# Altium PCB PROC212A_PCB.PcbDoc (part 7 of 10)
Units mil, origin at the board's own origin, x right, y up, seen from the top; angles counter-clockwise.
Board outline 3032.48 x 3598.78 mil, 4 copper layers (Top Layer, L2_GND1, L3_PWR1, Bottom Layer), stack 60.58 mil thick; 432 components, 310 nets, 7775 pads, 1236 vias.
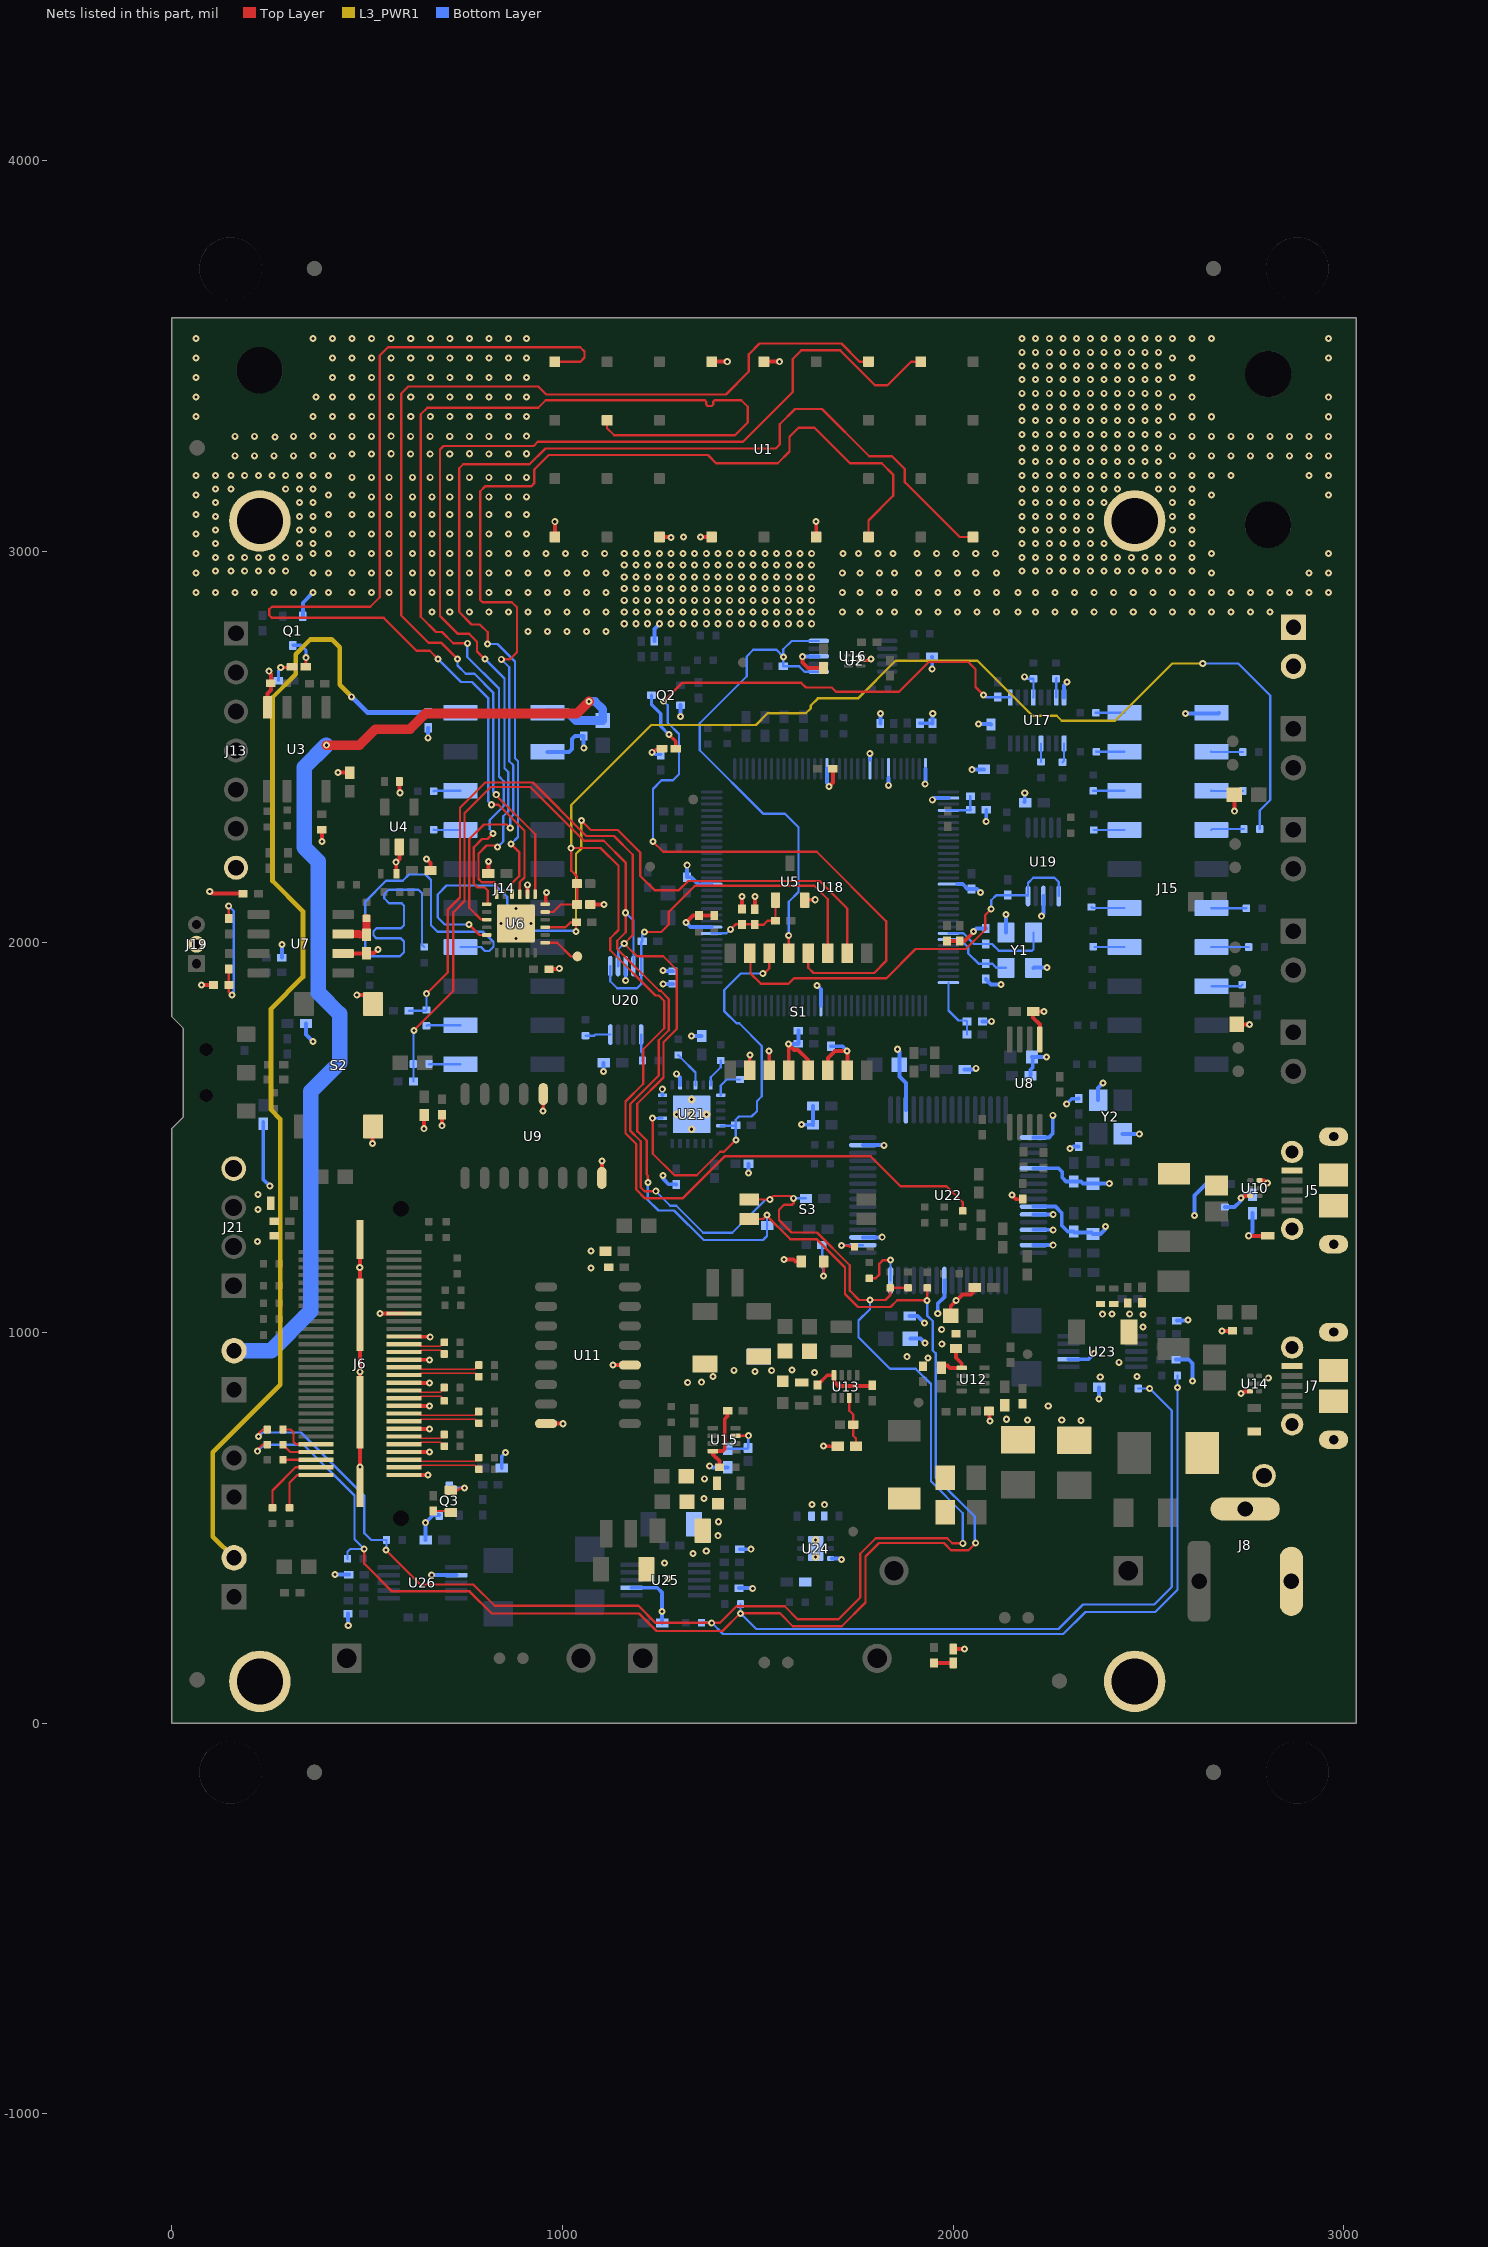
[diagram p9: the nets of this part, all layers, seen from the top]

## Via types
v1: diameter 18, hole 8, Top Layer to Bottom Layer, tented both sides, 1224 vias
v2: diameter 19.68, hole 7.87, Top Layer to Bottom Layer, tented both sides, 10 vias
v3: diameter 19.68, hole 7.87, Top Layer to Bottom Layer, 2 vias

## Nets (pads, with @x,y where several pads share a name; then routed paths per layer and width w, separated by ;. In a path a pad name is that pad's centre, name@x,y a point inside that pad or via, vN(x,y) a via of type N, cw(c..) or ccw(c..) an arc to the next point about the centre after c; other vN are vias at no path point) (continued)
GND: C1.1 C2.2 C3.2 C4.1 C5.2 C6.2 C7.2 C8.1 C9.1 C10.1 C11.2 C12.1 C13.1 C14.1 C15.1 C16.1 C17.2 C18.2 C19.2 C20.2 C21.1 C22.1 C23.2 C24.2 C25.2 C26.2 C27.2 C28.1 C29.2 C30.2 C31.1 C32.1 C33.1 C34.2 C35.2 C36.2 C37.2 C38.2 C39.2 C40.1 C41.2 C42.2 C43.1 C44.2 C45.2 C46.2 C47.1 C48.2 C49.2 C50.2 C51.2 C52.2 C53.2 C54.2 C55.1 C56.1 C57.2 C58.2 C59.2 C60.2 C61.2 C62.1 C63.1 C64.1 C65.1 C66.1 C67.1 C68.2 C69.2 C70.2 C71.1 C72.2 C73.2 C74.2 C75.1 C76.2 C77.2 C78.2 C79.2 C80.2 C81.2 C82.2 C83.1 C84.2 C85.2 C86.1 C87.2 C88.1 C89.2 C90.1 C91.2 C92.2 C93.1 C94.1 C95.2 C96.2 D4.1 D7.2 D9.2 J5.5 J5.6 J5.7 J5.8 J5.9 J5.10 J5.11 J6.18 J6.24 J6.30 J6.36 J6.42 J6.48 J6.54 J6.60 J6.MP1 J6.MP2 J6.MP3 J6.MP4 J7.5 J7.6 J7.7 J7.8 J7.9 J7.10 J7.11 J8.2 J8.3 J12.1 J12.2 J13.7 J14.4 J15.2 J19.2 J21.4 pad.TH2 pad.TH9 Q1.2 Q2.2 Q3.2 R3.1 R10.1 R13.1 R19.1 R25.2 R38.1 R63.1 R70.1 R72.1 R76.1 R84.1 R99.1 R120.2 R121.2 R123.1 R131.1 R152.1 R154.1 R176.1 R179.1 R182.2 R183.1 R193.1 R196.1 R199.1 R201.1 R207.1 R211.1 R213.1 R216.1 R220.1 S1.10 S1.11 S1.12 S1.13 S1.14 S1.15 S2.1 S2.2 TP7.1 U1.5 U1.6 U1.25 U1.27 U1.28 U1.30 U2.2 U3.4 U4.2 U5.2 U6.2 U6.24 U6.25 U7.2 U8.5 U9.8 U9.12 U10.3 U11.8 U11.12 U12.1 U13.8 U14.3 U15.8 U16.3 U17.8 U18.10 U18.17 U18.48 U18.55 U18.58 U18.64 U18.66 U18.80 U18.114 U19.3 U20.3 U21.2 U21.24 U21.25 U22.1 U22.5 U22.10 U22.11 U22.13 U22.15 U22.25 U22.35 U22.47 U22.51 U23.7 U24.3 U24.7 U25.7 U26.7 Y1.2 Y1.4 Y2.2 Y2.4 | length 8755.6
  Top Layer w8: U2.2@1763.78,2720.77 1783.13,2720.77 1787.14,2724.78 v1(1789.84,2724.78)
  Top Layer w10: v1(75.66,1889.9) 75.77,1890.01 C16.1@106.45,1890.01 ; v1(96.82,2129.42) 98.98,2129.42 104.03,2124.37 181.9,2124.37 C8.1@182.24,2124.03 ; U3.4@244.65,2601.15 244.65,2636.96 253.16,2645.47 R3.1@253.16,2662.39 253.16,2687.16 248.41,2691.91 v1(248.41,2693.53) ; R10.1@383.76,2287.35 383.76,2257.74 v1(384.05,2257.44) ; v1(425.53,2434.22) 425.75,2434 454.84,2434 C2.2@455.06,2433.78 ; U7.2@438.19,1970.7 497.48,1970.7 C15.1@498.41,1971.63 517.8,1971.63 v1(527.62,1981.45) ; v1(473.31,1864.09) 493.45,1864.09 515.04,1842.5 S2.1@515.04,1841.16 ; v1(480.87,1166.55) 481.52,1167.2 481.52,1206.04 J6.MP2@481.52,1013.52 ; J6.MP4@481.52,603.48 J6.MP3@481.52,796 J6.MP2@481.52,1046 ; v1(513.82,1484.39) 513.82,1526.94 S2.2@515.04,1528.17 ; v1(532.68,1049.1) 532.76,1049.03 594.23,1049.03 J6.18@594.31,1048.95 ; v1(573.87,2204.56) 582.13,2212.83 U4.2@582.13,2243.72 ; v1@574.3,2203.27 574.3,2175.54 C7.2@574.73,2175.11 ; C4.1@582.13,2411.48 583.04,2410.58 583.04,2383.26 v1(583.95,2382.35) ; J6.30@594.31,930.84 594.59,930.56 659.61,930.56 v1(659.89,930.29) ; J6.24@594.31,989.89 594.61,989.59 661.02,989.59 v1(661.32,989.3) ; J6.54@594.59,694.34 659.61,694.34 v1(659.89,694.07) ; J6.48@594.59,753.4 659.61,753.4 v1(659.89,753.12) ; J6.42@594.59,812.45 659.61,812.45 v1(659.89,812.18) ; J6.36@594.59,871.51 659.61,871.51 v1(659.89,871.23) ; J6.60@594.89,635.57 v1(655.32,635.58) ; v1(645.34,1522.12) 645.75,1522.52 C19.2@645.75,1557.03 ; v1(651.84,2212.32) 662.01,2202.15 R13.1@662.01,2183.31 ; v1(691.36,1529.81) 691.44,1529.88 691.44,1558.05 C20.2@691.51,1558.12 ; C6.2@810.41,2176.63 v1(810.41,2206.7) ; U6.2@910.26,2122.38 v1@910.28,2146.64 ; v1(950.36,1567.11) 950.64,1567.4 U9.12@950.64,1610.78 ; U6.24@955.53,2096.79 956.44,2096.79 957.17,2097.51 957.17,2125.24 v1(958.8,2126.87) ; U11.8@957.91,767.07 1001.29,767.07 v1(1001.58,766.79) ; R25.2@965.16,1930.78 965.87,1931.49 991.09,1931.49 v1(991.81,1932.21) ; U1.30@980.3,3037.2 v1@980.3,3076.35 ; R19.1@1070.97,2096.32 1105.71,2096.32 v1(1106.02,2096) ; U9.8@1100.64,1396.21 1100.64,1439.59 v1(1100.93,1439.88) ; v1(1128.81,917.36) 1129.1,917.07 U11.12@1172.48,917.07 ; U1.28@1248.02,3037.2 1274.99,3037.2 1276.62,3035.56 v1(1277.44,3035.56) ; v1(1316.07,2050.12) 1334.21,2068.25 C12.1@1349.45,2068.25 C11.2@1388.42,2068.25 ; v1(1353.24,3037.2) U1.27@1381.88,3037.2 ; U1.6@1378.64,3486.02 U1.6@1381.88,3486.02 v1(1421.79,3486.02) ; C50.2@1402.25,655.05 1402.25,671.29 1393.81,679.73 1393.01,679.73 1384.83,687.91 U15.8@1384.83,696.48 1409.69,696.48 1415.31,702.09 1415.31,779.14 1422.89,786.72 R76.1@1422.89,799.7 ; C9.1@1459.75,2084.66 1459.75,2116.11 v1(1459.94,2116.3) ; S1.10@1479.28,1671.68 1479.47,1671.87 1479.47,1710.47 v1(1479.66,1710.66) ; C10.1@1493.1,2084.79 1493.1,2116.24 v1(1493.29,2116.43) ; U1.5@1512.5,3486.02 U1.5@1515.73,3486.02 v1(1555.64,3486.02) ; v1(1528.75,1721.29) 1529.28,1720.77 S1.11@1529.28,1671.68 ; v1(1567.22,1187.13) 1592.17,1187.13 1597.06,1182.23 D4.1@1611.54,1182.23 ; v1(1578.3,1738.61) v1@1579.28,1737.63 ; S1.12@1579.28,1671.68 v1@1579.28,1737.63 ; v1(1614.53,2730.62) 1614.53,2715.83 1628.83,2701.53 C1.1@1668.49,2701.53 ; U5.2@1620.02,2107.41 1621.04,2108.43 v1(1646.99,2108.43) ; S1.13@1629.28,1671.68 1629.28,1697.58 1603.02,1723.84 1593.07,1723.84 v1@1579.28,1737.63 ; v1(1649.4,3076.5) 1649.59,3076.31 U1.25@1649.59,3037.2 ; C45.2@1653.1,866.18 1677.87,890.95 U13.8@1695.16,890.95 ; v1(1668.41,709.37) 1668.68,709.1 R84.1@1704.35,709.1 ; S1.14@1679.28,1671.68 1679.28,1702.97 1697.6,1721.29 v1(1728.75,1721.29) 1729.28,1720.77 S1.15@1729.28,1671.68 ; v1(1682.8,2398.85) 1692.1,2408.14 C3.2@1692.1,2443.69 ; U13.8@1694.55,890.35 1695.16,889.74 1695.16,874.8 1706.4,863.56 R70.1@1793.3,863.56 ; C40.1@1962.08,916.02 1985.54,916.02 1991.77,909.79 U12.1@2022.21,909.79 2022.21,920.9 2007.31,935.8 C39.2@2007.31,959.66 ; C13.1@1984.32,2003.06 2016.7,2003.06 C14.1@2017.02,2002.74 2029.36,2002.74 2051.88,2025.26 v1(2051.88,2026.83) ; C34.2@1994.09,1043.01 1994.09,1067.94 2023.69,1097.54 2045.59,1097.54 C27.2@2055.44,1107.39 ; D9.2@2000.53,189.9 2000.9,190.28 v1(2028.93,190.28) ; R72.1@2091.94,799.35 2093.12,798.17 2093.12,775.28 v1(2094.31,774.09) v1@2096.39,774.09 ; v1(2150.85,1352.14) 2161.38,1341.61 2178.03,1341.61 R38.1@2178.64,1342.22 ; U8.5@2222.05,1750.44 2222.05,1789.43 2205.08,1806.39 C18.2@2205.08,1822.34 2232.41,1822.34 v1(2232.71,1822.63) ; v1(2688.12,1004.64) v1(2688.12,1004.64) 2715.7,1004.59 R63.1@2715.76,1004.53 ; C5.2@2719.97,2376.89 2720.31,2376.55 v1(2720.31,2335.09) ; C17.2@2726.37,1789.73 2726.76,1789.34 v1(2758.48,1789.34) ; v1(2737.41,844.69) 2740.69,844.69 2745.8,849.81 U14.3@2760.01,849.81 ; v1@2757.22,1247.89 C22.1@2805.53,1247.89 ; U10.3@2784.61,1389.7 2795.9,1389.7 2802.85,1382.75 v1(2805.22,1382.75)
  Bottom Layer w8: 1347.35,2148.41 U18.17@1381.98,2148.41
  Bottom Layer w10: R176.1@233.75,1538.93 233.75,1391.93 v1(250.57,1375.12) ; R152.1@281.35,1960.2 281.35,1993.77 v1(281.56,1993.98) ; Q1.2@335.12,2834.44 335.13,2868.91 v1(361.31,2895.09) ; C68.2@343.2,1791.49 343.2,1763.83 v1(361.2,1745.83) ; v1(417.93,380.81) 418.43,380.3 R211.1@452.93,380.3 ; R220.1@451.06,280.61 451.06,250.95 v1(451.43,250.59) ; C95.2@649.67,469.17 v1(649.63,513.39) v1(649.63,513.39) 668.95,532.71 Q3.2@684.5,532.71 ; v1(655.31,2523.09) 655.91,2523.7 655.91,2548.05 C58.2@656.51,2548.65 ; v1(665.06,379.04) 665.22,379.2 U26.7@728.08,379.2 ; R201.1@844.37,653.22 844.37,683.48 v1(854.19,693.3) ; J14.4@961.45,2487.22 1016.67,2487.22 1023.95,2494.5 1023.95,2519.75 1032.12,2527.92 C60.2@1054.07,2527.92 1054.07,2497.2 v1(1054.54,2496.73) ; v1(1104.58,1668.43) 1104.58,1690.24 C76.2@1105.48,1691.14 ; v1(1161.87,1901.55) U20.3@1161.85,1938.43 ; U25.7@1176.87,346.87 1242.61,346.87 1254.34,335.13 v1(1254.34,285.8) 1254.81,285.33 1254.81,257.36 C96.2@1255.28,256.9 ; R99.1@1235.04,2770.65 1235.04,2802.06 v1(1248.07,2815.09) ; v1(1255.47,1623.3) 1255.47,1608.45 U21.24@1255.75,1608.17 ; v1(1256.93,1402.16) 1258.46,1400.63 1258.46,1393.08 1271.59,1379.95 1290.59,1379.95 R182.2@1290.96,1379.59 ; v1(1257.56,1927.68) 1258.79,1926.46 1281.47,1926.46 R154.1@1282.7,1925.23 ; v1(1257.8,1893.15) v1(1257.8,1893.15) 1282.8,1893.21 C67.1@1282.86,1893.26 ; v1(1291.68,1662.85) 1301.03,1653.5 U21.2@1301.03,1633.76 ; v1(1302.24,2577.12) 1302.39,2577.27 Q2.2@1302.39,2606.61 ; v1(1316.07,2050.12) 1328.01,2038.18 U18.10@1381.98,2038.18 ; v1(1319.24,2196.86) 1319.24,2166.5 C64.1@1318.67,2165.92 1329.84,2165.92 1347.35,2148.41 ; v1(1330.48,1759.57) C72.2@1356.27,1759.57 ; v1(1376.89,659.05) 1379.6,659.05 1383.6,655.04 R199.1@1423.17,655.04 ; R216.1@1452.02,345.76 1486.52,345.76 v1(1487.02,345.25) ; R207.1@1453.89,445.45 v1(1482.96,445.5) ; R179.1@1476.27,1432.5 1476.27,1408.81 v1(1476.55,1408.54) ; v1(1578.3,1738.61) 1578.84,1739.15 1603.28,1739.15 C73.2@1603.82,1739.69 C71.1@1603.82,1773.19 ; v1(1611.5,1532.71) 1611.78,1532.43 1641,1532.43 C81.2@1641.28,1532.15 1641.28,1580.43 C80.2@1641.12,1580.58 ; v1(1614.53,2730.62) 1615.34,2731.44 1655.57,2731.44 U16.3@1655.91,2731.78 ; v1(1652.07,1888.59) 1661.51,1879.15 U18.114@1661.51,1837.39 ; U18.48@1677.26,2443.69 1677.26,2407.1 1682.8,2401.55 v1(1682.8,2398.85) ; C70.2@1687.52,1733.29 1716.76,1733.29 v1(1728.75,1721.29) ; U24.3@1689.31,421.71 1710.18,421.71 1712.53,419.35 v1@1714.05,419.35 ; U22.35@1769.04,1243.77 1817.86,1243.77 v1(1818.51,1244.42) ; U22.47@1769.04,1480 1822.81,1480 v1(1823.09,1479.72) ; v1(1786.73,2483.2) 1787.43,2482.5 U18.55@1787.43,2467.25 ; R123.1@1813.42,2559.71 1813.68,2559.97 1813.68,2584.76 v1(1813.94,2585.02) ; U18.58@1834.8,2420.13 1834.8,2401.62 v1(1834.93,2401.49) ; v1(1858.09,1725.63) 1858.09,1724.82 1862.74,1720.17 1862.74,1686.03 C75.1@1862.4,1685.69 1862.4,1655.69 1879.27,1638.82 U22.51@1879.27,1570.55 ; C89.2@1888.78,1042.92 1909.16,1042.92 v1(1927.14,1024.94) ; C90.1@1890.74,984.52 1917.09,984.52 v1(1928.5,973.11) ; R120.2@1915.24,2560.24 R121.2@1947.24,2560.24 ; v1(1928.72,2405.11) 1929.16,2405.56 1929.16,2443.62 U18.64@1929.23,2443.69 ; C57.2@1945.98,2729.57 1946.6,2728.95 v1(1946.6,2699.1) ; v1(1946.83,2364.39) 1951.33,2368.88 U18.66@1988.28,2368.88 ; R121.2@1947.45,2560.03 1947.7,2560.29 1947.7,2585.09 v1(1947.96,2585.35) ; v1(1960.74,1048.82) 1960.74,1074.38 1977.7,1091.34 U22.25@1977.7,1133.54 ; U18.80@2011.84,2148.41 2024.84,2148.41 2037.44,2135.82 C63.1@2047.17,2135.82 C63.1@2047.41,2135.82 ; C77.2@2029.7,1673.9 2053.1,1673.9 2056.11,1676.91 v1(2058.27,1676.91) ; C63.1@2047.52,2135.47 2061.69,2135.47 2069.74,2127.42 v1(2069.91,2127.42) ; v1(2048.55,2441.38) 2048.99,2441.82 2078.72,2441.82 R131.1@2079.17,2442.26 ; v1(2051.88,2026.83) 2052.48,2026.83 2060.32,2034.66 C65.1@2084.03,2034.66 ; v1(2065.4,2557.97) 2096.2,2557.97 C59.2@2096.89,2557.27 ; C69.2@2075.24,1796.71 2075.5,1796.97 2098.36,1796.97 v1(2098.58,1797.19) ; C66.1@2084.03,1905.54 2084.03,1903.58 2088.88,1898.73 2089.75,1898.73 2096.77,1891.71 2122.43,1891.71 v1(2122.94,1891.2) ; v1@2084.85,2308.88 C62.1@2084.85,2338.76 ; Y1.4@2135.24,2024.64 v1(2135.24,2070.89) ; C61.2@2183.3,2359.14 2183.48,2359.31 v1(2183.48,2382.19) ; C78.2@2198.09,1657.84 2198.09,1673.11 2203.9,1678.93 2203.9,1703.93 C74.2@2201.84,1705.99 v1(2238.88,1706.01) ; U22.15@2206.05,1224.09 2256.19,1224.09 v1(2256.42,1223.86) ; U22.13@2206.05,1263.46 2256.19,1263.46 v1(2256.42,1263.23) ; U22.11@2206.05,1302.83 2256.19,1302.83 v1(2256.42,1302.6) ; U22.10@2206.05,1322.52 2261.73,1322.52 2278.33,1305.92 2278.33,1274.16 2293.63,1258.85 C86.1@2308.76,1258.85 ; U22.5@2206.05,1420.94 2269.52,1420.94 2279.42,1411.05 2279.42,1396.9 2289.23,1387.08 C83.1@2308.76,1387.08 2327.1,1387.08 2332.6,1381.59 C84.2@2358.23,1381.59 v1@2399.89,1381.59 ; U22.1@2206.05,1499.68 2245.24,1499.68 2255.27,1509.72 v1(2255.27,1556.56) ; Y1.2@2206.11,1934.09 2206.76,1934.73 v1(2240.89,1934.73) ; v1(2226.74,2066.26) 2226.74,2068.42 2231.23,2072.9 U19.3@2231.26,2117.88 ; U17.8@2284.12,2626.66 2284.12,2657.48 2291.94,2665.3 v1(2291.94,2665.92) ; v1(2290.94,1585.83) 2303.94,1598.84 2320.99,1598.84 C79.2@2321.57,1599.41 ; U23.7@2295.6,931.99 2347.2,931.99 v1(2361.31,946.09) ; v1(2299.72,1471.12) 2301.88,1471.12 2307.74,1476.98 C82.2@2321.74,1476.98 ; C86.1@2310.74,1256.87 C87.2@2353.98,1256.87 ; C87.2@2358.23,1252.63 2377.46,1252.63 2388.84,1264.01 2388.84,1269.96 v1(2390.37,1271.49) ; Y2.4@2371.19,1595.56 2371.19,1626.42 v1(2384.07,1639.3) ; v1(2373.83,830.58) 2373.83,860.14 C91.2@2373.9,860.2 ; Y2.2@2434.18,1508.94 2476.75,1508.94 v1(2476.79,1508.98) ; R196.1@2570.75,930.88 2603.52,930.88 2613.36,921.04 v1(2613.36,876.19) ; R193.1@2572.62,1030.57 2573.35,1031.3 2601.2,1031.3 v1(2601.93,1032.03) ; v1(2594.8,2585.05) 2679.11,2585.05 J15.2@2681.27,2587.22 ; v1(2618.26,1300.05) 2618.26,1351.31 2647.55,1380.6 R183.1@2670.87,1380.6 ; v1(2756.96,1248.15) 2766.98,1258.16 C85.2@2766.98,1306.06
  other v1: 1270.09,370.27 1261.48,410.5 1714.1,419.4 1333.64,434.4 1368.05,440.59 1398.31,480.09 1399.66,515.86 1670.92,559.48 1638.64,559.76 1362.13,575.61 1363.58,625.79 481.11,655.97 2327.46,775.49 2278.29,775.93 2190.12,776.82 2136.74,778.31 2243.71,812.17 1320.56,872.61 1355.95,873.16 2807.12,883.5 2376.79,886.2 2470.94,887.29 1385.3,887.99 1645.53,898.39 481.89,899.85 1492.4,900.52 1535.62,902.74 1438.82,903.6 1587.61,904.86 2425.31,924.09 1936.12,935.55 1882.46,938.37 1971.14,971.13 1970.86,1008.13 2486.72,1014.91 2486.76,1046.33 2382.19,1047.21 2452.22,1047.49 2407.38,1047.85 2008.02,1081.86 1072.75,1165.5 1072.54,1209.33 219.39,1233.58 219.9,1315.67 219.9,1354.12 2399.98,1381.49 910.31,2146.66 2084.9,2308.83 911.31,2795.09 961.31,2795.09 1011.31,2795.09 1061.31,2795.09 1111.31,2795.09 1158.07,2815.09 1188.07,2815.09 1218.07,2815.09 1278.07,2815.09 1308.07,2815.09 1338.07,2815.09 1368.07,2815.09 1398.07,2815.09 1428.07,2815.09 1458.07,2815.09 1488.07,2815.09 1518.07,2815.09 1548.07,2815.09 1578.07,2815.09 1608.07,2815.09 1638.07,2815.09 666.31,2845.09 711.31,2845.09 761.31,2845.09 811.31,2845.09 861.31,2845.09 911.31,2845.09 961.31,2845.09 1011.31,2845.09 1061.31,2845.09 1111.31,2845.09 1158.07,2845.09 1188.07,2845.09 1218.07,2845.09 1248.07,2845.09 1278.07,2845.09 1308.07,2845.09 1338.07,2845.09 1368.07,2845.09 1398.07,2845.09 1428.07,2845.09 1458.07,2845.09 1488.07,2845.09 1518.07,2845.09 1548.07,2845.09 1578.07,2845.09 1608.07,2845.09 1638.07,2845.09 1716.31,2845.09 1761.31,2845.09 1811.31,2845.09 1849.77,2845.09 1911.31,2845.09 1961.31,2845.09 2011.31,2845.09 2061.31,2845.09 2111.31,2845.09 2166.31,2845.09 2211.31,2845.09 2261.31,2845.09 2311.31,2845.09 2361.31,2845.09 2411.31,2845.09 2461.31,2845.09 2511.31,2845.09 2561.31,2845.09 2611.31,2845.09 2661.31,2845.09 2711.31,2845.09 2761.31,2845.09 2811.31,2845.09 1158.07,2875.09 1188.07,2875.09 1218.07,2875.09 1248.07,2875.09 1278.07,2875.09 1308.07,2875.09 1338.07,2875.09 1368.07,2875.09 1398.07,2875.09 1428.07,2875.09 1458.07,2875.09 1488.07,2875.09 1518.07,2875.09 1548.07,2875.09 1578.07,2875.09 1608.07,2875.09 1638.07,2875.09 61.31,2895.09 111.31,2895.09 161.31,2895.09 211.31,2895.09 261.31,2895.09 311.31,2895.09 401.31,2895.09 461.31,2895.09 511.31,2895.09 556.31,2895.09 616.31,2895.09 666.31,2895.09 711.31,2895.09 761.31,2895.09 811.31,2895.09 861.31,2895.09 911.31,2895.09 961.31,2895.09 1011.31,2895.09 1061.31,2895.09 1111.31,2895.09 1716.31,2895.09 1761.31,2895.09 1811.31,2895.09 1849.77,2895.09 1911.31,2895.09 1961.31,2895.09 2011.31,2895.09 2061.31,2895.09 2111.31,2895.09 2166.31,2895.09 2211.31,2895.09 2261.31,2895.09 2311.31,2895.09 2361.31,2895.09 2411.31,2895.09 2461.31,2895.09 2511.31,2895.09 2561.31,2895.09 2611.31,2895.09 2661.31,2895.09 2711.31,2895.09 2761.31,2895.09 2811.31,2895.09 2861.31,2895.09 2911.31,2895.09 2961.31,2895.09 1158.07,2905.09 1188.07,2905.09 1218.07,2905.09 1248.07,2905.09 1278.07,2905.09 1308.07,2905.09 1338.07,2905.09 1368.07,2905.09 1398.07,2905.09 1428.07,2905.09 1458.07,2905.09 1488.07,2905.09 1518.07,2905.09 1548.07,2905.09 1578.07,2905.09 1608.07,2905.09 1638.07,2905.09 1158.07,2935.09 1188.07,2935.09 1218.07,2935.09 1248.07,2935.09 1278.07,2935.09 1308.07,2935.09 1338.07,2935.09 1368.07,2935.09 1398.07,2935.09 1428.07,2935.09 1458.07,2935.09 1488.07,2935.09 1518.07,2935.09 1548.07,2935.09 1578.07,2935.09 1608.07,2935.09 1638.07,2935.09 61.31,2945.09 361.31,2945.09 401.31,2945.09 461.31,2945.09 511.31,2945.09 556.31,2945.09 616.31,2945.09 666.31,2945.09 711.31,2945.09 761.31,2945.09 811.31,2945.09 861.31,2945.09 911.31,2945.09 961.31,2945.09 1011.31,2945.09 1061.31,2945.09 1111.31,2945.09 1716.31,2945.09 1761.31,2945.09 1811.31,2945.09 1849.77,2945.09 1911.31,2945.09 1961.31,2945.09 2011.31,2945.09 2058.07,2945.09 2111.31,2945.09 2661.31,2945.09 2911.31,2945.09 2961.31,2945.09 111.31,2950.09 151.31,2950.09 186.31,2950.09 221.31,2950.09 256.31,2950.09 291.31,2950.09 2176.31,2950.09 2211.31,2950.09 2246.31,2950.09 2281.31,2950.09 2316.31,2950.09 2351.31,2950.09 2386.31,2950.09 2421.31,2950.09 2456.31,2950.09 2491.31,2950.09 2526.31,2950.09 2561.31,2950.09 2611.31,2950.09 1158.07,2965.09 1188.07,2965.09 1218.07,2965.09 1248.07,2965.09 1278.07,2965.09 1308.07,2965.09 1338.07,2965.09 1368.07,2965.09 1398.07,2965.09 1428.07,2965.09 1458.07,2965.09 1488.07,2965.09 1518.07,2965.09 1548.07,2965.09 1578.07,2965.09 1608.07,2965.09 1638.07,2965.09 111.31,2985.09 151.31,2985.09 186.31,2985.09 221.31,2985.09 256.31,2985.09 291.31,2985.09 326.31,2985.09 2176.31,2985.09 2211.31,2985.09 2246.31,2985.09 2281.31,2985.09 2316.31,2985.09 2351.31,2985.09 2386.31,2985.09 2421.31,2985.09 2456.31,2985.09 2491.31,2985.09 2526.31,2985.09 2561.31,2985.09 2611.31,2985.09 61.31,2995.09 361.31,2995.09 401.31,2995.09 461.31,2995.09 511.31,2995.09 556.31,2995.09 616.31,2995.09 666.31,2995.09 711.31,2995.09 761.31,2995.09 811.31,2995.09 861.31,2995.09 908.07,2995.09 958.07,2995.09 1008.07,2995.09 1058.07,2995.09 1108.07,2995.09 1158.07,2995.09 1188.07,2995.09 1218.07,2995.09 1248.07,2995.09 1278.07,2995.09 1308.07,2995.09 1338.07,2995.09 1368.07,2995.09 1398.07,2995.09 1428.07,2995.09 1458.07,2995.09 1488.07,2995.09 1518.07,2995.09 1548.07,2995.09 1578.07,2995.09 1608.07,2995.09 1638.07,2995.09 1718.07,2995.09 1758.07,2995.09 1808.07,2995.09 1846.53,2995.09 1908.07,2995.09 1958.07,2995.09 2008.07,2995.09 2058.07,2995.09 2108.07,2995.09 2661.31,2995.09 2961.31,2995.09 111.31,3020.09 326.31,3020.09 361.31,3020.09 2176.31,3020.09 2211.31,3020.09 2246.31,3020.09 2281.31,3020.09 2316.31,3020.09 2351.31,3020.09 2386.31,3020.09 2561.31,3020.09 2611.31,3020.09 1309.69,3037.17 61.31,3045.09 401.31,3045.09 461.31,3045.09 511.31,3045.09 556.31,3045.09 616.31,3045.09 666.31,3045.09 711.31,3045.09 761.31,3045.09 811.31,3045.09 861.31,3045.09 908.07,3045.09 111.31,3055.09 326.31,3055.09 361.31,3055.09 2176.31,3055.09 2211.31,3055.09 2246.31,3055.09 2281.31,3055.09 2316.31,3055.09 2351.31,3055.09 2561.31,3055.09 2611.31,3055.09 980.28,3076.37 111.31,3090.09 326.31,3090.09 361.31,3090.09 2176.31,3090.09 2211.31,3090.09 2246.31,3090.09 2281.31,3090.09 2316.31,3090.09 2351.31,3090.09 2561.31,3090.09 2611.31,3090.09 61.31,3095.09 401.31,3095.09 461.31,3095.09 511.31,3095.09 556.31,3095.09 616.31,3095.09 666.31,3095.09 711.31,3095.09 761.31,3095.09 811.31,3095.09 861.31,3095.09 908.07,3095.09 111.31,3125.09 326.31,3125.09 361.31,3125.09 2176.31,3125.09 2211.31,3125.09 2246.31,3125.09 2281.31,3125.09 2316.31,3125.09 2351.31,3125.09 2386.31,3125.09 2561.31,3125.09 2611.31,3125.09 511.31,3140.09 556.31,3140.09 616.31,3140.09 666.31,3140.09 711.31,3140.09 761.31,3140.09 811.31,3140.09 861.31,3140.09 908.07,3140.09 61.31,3145.09 401.31,3145.09 461.31,3145.09 2661.31,3145.09 2961.31,3145.09 111.31,3160.09 151.31,3160.09 291.31,3160.09 326.31,3160.09 361.31,3160.09 2176.31,3160.09 2211.31,3160.09 2246.31,3160.09 2281.31,3160.09 2316.31,3160.09 2351.31,3160.09 2386.31,3160.09 2421.31,3160.09 2526.31,3160.09 2561.31,3160.09 2611.31,3160.09 461.31,3190.09 511.31,3190.09 556.31,3190.09 616.31,3190.09 661.31,3190.09 711.31,3190.09 761.31,3190.09 811.31,3190.09 861.31,3190.09 908.07,3190.09 61.31,3195.09 111.31,3195.09 151.31,3195.09 186.31,3195.09 221.31,3195.09 256.31,3195.09 291.31,3195.09 326.31,3195.09 361.31,3195.09 401.31,3195.09 2176.31,3195.09 2211.31,3195.09 2246.31,3195.09 2281.31,3195.09 2316.31,3195.09 2351.31,3195.09 2386.31,3195.09 2421.31,3195.09 2456.31,3195.09 2491.31,3195.09 2526.31,3195.09 2561.31,3195.09 2611.31,3195.09 2661.31,3195.09 2711.31,3195.09 2911.31,3195.09 2961.31,3195.09 2176.31,3230.09 2211.31,3230.09 2246.31,3230.09 2281.31,3230.09 2316.31,3230.09 2351.31,3230.09 2386.31,3230.09 2421.31,3230.09 2456.31,3230.09 2491.31,3230.09 2526.31,3230.09 161.31,3245.09 211.31,3245.09 261.31,3245.09 311.31,3245.09 361.43,3245.3 411.31,3245.09 2561.31,3245.09 2611.31,3245.09 2661.31,3245.09 2711.31,3245.09 2761.31,3245.09 2811.31,3245.09 2861.31,3245.09 2911.31,3245.09 2961.31,3245.09 461.31,3250.09 511.31,3250.09 561.43,3250.3 611.31,3250.09 661.31,3250.09 711.31,3250.09 761.43,3250.3 811.31,3250.09 861.31,3250.09 908.19,3250.3 2176.31,3265.09 2211.31,3265.09 2246.31,3265.09 2281.31,3265.09 2316.31,3265.09 2351.31,3265.09 2386.31,3265.09 2421.31,3265.09 2456.31,3265.09 2491.31,3265.09 2526.31,3265.09 263.55,3293.38 161.31,3295.09 211.31,3295.09 311.31,3295.09 361.43,3295.3 411.31,3295.09 461.31,3295.09 511.31,3295.09 561.43,3295.3 611.31,3295.09 661.31,3295.09 711.31,3295.09 761.31,3295.09 811.31,3295.09 861.31,3295.09 908.19,3295.3 2561.31,3295.09 2611.31,3295.09 2661.31,3295.09 2711.31,3295.09 2761.31,3295.09 2811.31,3295.09 2861.31,3295.09 2911.31,3295.09 2961.31,3295.09 2176.31,3300.09 2211.31,3300.09 2246.31,3300.09 2281.31,3300.09 2316.31,3300.09 2351.31,3300.09 2386.31,3300.09 2421.31,3300.09 2456.31,3300.09 2491.31,3300.09 2526.31,3300.09 2176.31,3335.09 2211.31,3335.09 2246.31,3335.09 2281.31,3335.09 2316.31,3335.09 2351.31,3335.09 2386.31,3335.09 2421.31,3335.09 2456.31,3335.09 2491.31,3335.09 2526.31,3335.09 61.43,3345.3 361.43,3345.3 411.43,3345.3 461.43,3345.3 511.43,3345.3 561.43,3345.3 611.43,3345.3 661.43,3345.3 711.43,3345.3 761.43,3345.3 811.43,3345.3 861.43,3345.3 908.19,3345.3 2561.31,3345.09 2611.31,3345.09 2661.31,3345.09 2961.31,3345.09 2176.31,3370.09 2211.31,3370.09 2246.31,3370.09 2281.31,3370.09 2316.31,3370.09 2351.31,3370.09 2386.31,3370.09 2421.31,3370.09 2456.31,3370.09 2491.31,3370.09 2526.31,3370.09 61.43,3395.3 411.43,3395.3 461.43,3395.3 511.43,3395.3 561.43,3395.3 611.43,3395.3 661.43,3395.3 711.43,3395.3 761.43,3395.3 811.43,3395.3 861.43,3395.3 908.19,3395.3 2561.31,3395.09 2611.31,3395.09 2961.31,3395.09 368.41,3396 2176.31,3405.09 2211.31,3405.09 2246.31,3405.09 2281.31,3405.09 2316.31,3405.09 2351.31,3405.09 2386.31,3405.09 2421.31,3405.09 2456.31,3405.09 2491.31,3405.09 2526.31,3405.09 2176.31,3440.09 2211.31,3440.09 2246.31,3440.09 2281.31,3440.09 2316.31,3440.09 2351.31,3440.09 2386.31,3440.09 2421.31,3440.09 2456.31,3440.09 2491.31,3440.09 2526.31,3440.09 61.43,3445.3 411.43,3445.3 461.43,3445.3 511.43,3445.3 561.43,3445.3 611.43,3445.3 661.43,3445.3 711.43,3445.3 761.43,3445.3 811.43,3445.3 861.43,3445.3 908.19,3445.3 2561.31,3445.09 2611.31,3445.09 2176.31,3475.09 2211.31,3475.09 2246.31,3475.09 2281.31,3475.09 2316.31,3475.09 2351.31,3475.09 2386.31,3475.09 2421.31,3475.09 2456.31,3475.09 2491.31,3475.09 2526.31,3475.09 61.43,3495.3 411.43,3495.3 461.43,3495.3 511.43,3495.3 561.43,3495.3 611.43,3495.3 661.43,3495.3 711.43,3495.3 761.43,3495.3 811.43,3495.3 861.43,3495.3 908.19,3495.3 2561.31,3495.09 2611.31,3495.09 2961.31,3495.09 2176.31,3510.09 2211.31,3510.09 2246.31,3510.09 2281.31,3510.09 2316.31,3510.09 2351.31,3510.09 2386.31,3510.09 2421.31,3510.09 2456.31,3510.09 2491.31,3510.09 2526.31,3510.09 61.43,3545.3 361.43,3545.3 411.43,3545.3 461.43,3545.3 511.43,3545.3 561.43,3545.3 611.43,3545.3 661.43,3545.3 711.43,3545.3 761.43,3545.3 811.43,3545.3 861.43,3545.3 908.19,3545.3 2176.31,3545.09 2211.31,3545.09 2246.31,3545.09 2281.31,3545.09 2316.31,3545.09 2351.31,3545.09 2386.31,3545.09 2421.31,3545.09 2456.31,3545.09 2491.31,3545.09 2526.31,3545.09 2561.31,3545.09 2611.31,3545.09 2661.31,3545.09 2961.31,3545.09
  other v2: 1330.55,1520.77 1292.36,1558.96 1330.55,1558.96 1368.74,1558.96 1330.55,1597.15 880.73,2009.38 842.54,2047.57 880.73,2047.57 918.92,2047.57 880.73,2085.76
  other v3: 1648.06,425.69 1648.06,469
HOST_CLK_REQ: TP4.1 U6.19 | length 97.1
  Top Layer w5.9: U6.19@955.53,1998.36 986.8,1998.36 1021.84,1963.33 TP4.1@1038.08,1963.33
HOSTIRQ_FTDI_IN: R51.1 U22.32 | length 142.3
  Top Layer w5.9: R51.1@1785.48,1139.1 1801.71,1139.1 1811.31,1148.69 1811.31,1176.49 1820.55,1185.73 v1(1839.95,1185.73)
  Bottom Layer w5.9: U22.32@1839.93,1133.56 v1(1839.95,1185.73)
HOSTIRQ_FTDI_OUT: R47.1 U22.34 | length 90.6
  Top Layer w5.9: v1(1714.05,1222.79) 1732.71,1222.79 1735.83,1219.68 R47.1@1747.84,1219.68
  Bottom Layer w5.9: v1(1714.05,1222.79) 1715.35,1224.09 U22.34@1769.04,1224.09
I2C_SCL: R55.2 R82.1 R161.1 R162.1 R186.1 R198.2 R209.2 R218.2 S3.2 U20.2 | length 8147.8
  Top Layer w5.9: v1(218.77,696.44) 221.09,698.76 221.09,702.52 231.79,713.22 R82.1@244.09,713.22 ; v1(492.31,446.09) 492.31,408.62 563.38,337.55 762.12,337.55 818.96,280.7 1195.68,280.7 1240.34,236.04 1409.87,236.04 1455.21,281.38 v1(1455.83,281.38) 1556.83,281.38 1589.67,248.53 1715.07,248.53 1775.73,309.19 1775.73,426.98 1810.05,461.31 1976.42,461.31 1994.93,442.8 2039.17,442.8 v1(2057.92,461.55) ; v1(651.65,1867.77) 706.48,1922.6 706.48,2083.27 737.4,2114.18 737.4,2344.18 801.96,2408.74 924.13,2408.74 1061.05,2271.83 1131.57,2271.83 1179.97,2223.43 1179.97,2017.84 v1(1158.1,1995.97) 1190.58,1963.49 1258.06,1963.49 1292.31,1929.24 1292.31,1777.28 1258.39,1743.36 1258.39,1653.28 1191.29,1586.18 1191.29,1516.01 1215.54,1491.76 1215.54,1405.05 1218.53,1402.06 v1(1218.53,1384.25) ; S3.2@1478.09,1290.87 1513.42,1290.87 v1(1523.43,1300.89) ; v1@1523.43,1298.88 1582.86,1239.45 1650.22,1239.45 1723.14,1166.52 1723.14,1099.17 1756.73,1065.58 1840.03,1065.58 1857.15,1082.7 v1(1933.52,1082.7) 1933.91,1083.1 R55.2@1933.91,1114.63
  Bottom Layer w5.9: v1(218.77,696.44) 235.55,713.22 337.18,713.22 467.31,583.09 467.31,471.09 v1@489.31,449.09 ; R209.2@449.3,420.9 449.3,439.09 456.31,446.09 486.72,446.09 486.72,446.5 v1@489.31,449.09 ; v1(492.31,446.09) v1@489.31,449.09 ; R161.1@606.8,1824.45 650.06,1824.45 R162.1@651.56,1825.95 651.56,1867.68 v1(651.65,1867.77) ; U20.2@1142.17,1938.43 1142.74,1939.01 1142.74,1981.91 1156.8,1995.97 v1(1158.1,1995.97) ; v1(1218.53,1384.25) 1218.53,1339.84 1245.42,1312.95 1285.63,1312.95 1361.35,1237.22 1513.02,1237.22 1523.49,1247.69 1523.49,1273.3 R186.1@1524.49,1274.3 1523.43,1275.36 v1(1523.43,1300.89) ; R218.2@1455.65,305.16 1455.65,281.55 v1(1455.83,281.38) ; v1@1456.03,281.38 1496.14,241.27 2270.03,241.27 2332.78,304.01 2515.06,304.01 2559.97,348.92 2559.97,800.82 v1(2503.48,857.31) 2503.19,857.02 R198.2@2474.39,857.02 ; v1(1933.52,1082.7) 1933.52,1043.95 1947.87,1029.6 1947.87,954.56 1955.31,947.12 1955.31,628.87 2055.79,528.39 2055.79,463.68 v1(2057.92,461.55)
I2C_SDA: R53.2 R54.2 R80.1 R172.1 R175.1 R184.1 R197.2 R204.2 R222.2 S3.1 U20.4 | length 8398.9
  Top Layer w5.9: v1(221.52,734.1) 223.84,736.41 223.84,743.65 232.24,752.06 R80.1@244.59,752.06 ; v1(547.65,443.41) 635.96,355.09 771.75,355.09 826.29,300.55 1194.76,300.55 1238.43,256.88 v1@1381.41,256.88 ; v1(619.51,1773.16) 619.51,1774.12 720.58,1875.2 720.58,2076.37 749.3,2105.08 749.3,2330.08 816.06,2396.84 917.52,2396.84 1054.79,2259.58 1105.82,2259.58 1161.59,2203.81 v1(1161.59,2075.1) 1162.03,2074.66 1162.03,2025.28 1140.15,2003.4 1140.15,1982.6 1247.55,1875.2 1251.29,1875.2 1272.2,1854.29 1272.2,1774.36 1246.49,1748.65 1246.49,1658.21 1173.13,1584.85 1173.13,1517.34 1200.58,1489.9 1200.58,1371.46 1209.94,1362.09 v1(1238.89,1362.09) ; v1(1381.98,257.04) 1403.11,257.04 1445.4,299.33 1569.03,299.33 1601.96,266.39 1706.59,266.39 1762.14,321.94 1762.14,434.11 1801.87,473.84 1984.8,473.84 1997.89,460.75 v1(2024.86,460.75) ; S3.1@1478.09,1340.87 v1(1530.66,1340.87) 1539.62,1349.83 1582.64,1349.83 1588.43,1344.05 v1(1591.7,1344.05) 1591.7,1331.29 1587.9,1327.49 1567.38,1327.49 1554.43,1314.53 1554.43,1288.52 1586.4,1256.55 1651.64,1256.55 1735.34,1172.85 1735.34,1107.61 1759.42,1083.53 v1(1787.08,1083.53) 1827.09,1083.53 1838.78,1095.22 R54.2@1838.78,1114.72 1839.21,1115.15 R53.2@1884.81,1115.15
  Bottom Layer w5.9: v1(221.52,734.1) 231.83,744.41 330.21,744.41 492.73,581.89 492.73,486.67 510.23,469.17 R204.2@549.29,469.17 549.29,445.04 v1(547.65,443.41) ; R175.1@618.35,1642.87 618.35,1687.33 R172.1@617.81,1687.88 618.66,1688.73 618.66,1772.3 v1(619.51,1773.16) ; v1(1161.59,2075.1) 1181.54,2055.16 U20.4@1181.54,1938.43 ; v1(1238.89,1362.09) 1276.13,1324.85 1291.35,1324.85 1360.61,1255.59 1434.89,1255.59 1519.16,1339.87 1529.65,1339.87 v1(1530.66,1340.87) ; R222.2@1355.66,256.9 1381.84,256.9 v1(1381.98,257.04) 1410.72,228.29 2282.08,228.29 2338.79,285 2517.89,285 2574.38,341.5 v1(2574.38,859.83) R197.2@2574.38,890.28 ; v1(1591.7,1344.05) 1591.92,1343.83 R184.1@1623.26,1343.83 ; v1(1787.08,1083.53) 1787.08,1060.14 1757.75,1030.8 1757.75,988.5 1838.98,907.26 1904.51,907.26 1943.38,868.39 1943.38,619.28 2024.86,537.8 v1(2024.86,460.75)
LP_SPI_CLK: J14.13 R151.2 | length 1408.5
  Bottom Layer w5.9: R151.2@645.75,1987.25 640.31,1992.69 640.31,2125.09 631.31,2134.09 554.31,2134.09 543.31,2123.09 543.31,2112.09 556.31,2099.09 588.31,2099.09 594.31,2093.09 594.31,2072 594.31,2043.15 586.54,2035.38 523.94,2035.38 516.17,2027.61 516.17,2017.25 523.94,2009.48 586.54,2009.48 594.31,2001.71 594.31,1997.14 594.31,1974.09 583.71,1963.5 510.9,1963.5 495.31,1979.09 495.31,2104.09 548.31,2157.09 590.75,2157.09 606.75,2173.09 649.31,2173.09 663.31,2159.09 663.31,2043.09 680.31,2026.09 797.31,2026.09 823.31,2000.09 823.31,1988.09 812.31,1977.09 801.31,1977.09 791.18,1987.22 J14.13@739.01,1987.22
LP_SPI_CS: J15.16 R158.1 | length 80.4
  Bottom Layer w5.9: J15.16@2661.45,1887.22 2736.33,1887.22 R158.1@2740.23,1891.11
LP_SPI_MISO: J15.14 R150.1 | length 95.6
  Bottom Layer w5.9: J15.14@2661.28,1987.21 R150.1@2756.84,1987.21
LP_SPI_MOSI: J15.12 R147.1 | length 90
  Bottom Layer w5.9: J15.12@2661.27,2087.22 2662.03,2086.46 R147.1@2750.94,2086.46
LVDS_CLK_DC_PWM_AUTO_CTRL_GPIO: U1.14 U6.7 | length 2769.5
  Top Layer w5.9: v1(756.31,2765.09) 720.31,2765.09 691.31,2794.09 676.31,2794.09 637.23,2833.17 637.23,3351.46 654.05,3368.27 658.94,3368.27 659.05,3368.17 937.99,3368.17 957.16,3387.33 1343.5,3387.33 1364.35,3387.33 1367.93,3383.75 1367.93,3376.34 1371.51,3372.76 1382.25,3372.76 1385.83,3376.34 1385.83,3383.75 1389.41,3387.33 1412.6,3387.33 1457.93,3387.33 1474.31,3370.96 1474.31,3330.36 1441.39,3297.44 1132.27,3297.44 1114.16,3315.55 U1.14@1114.16,3336.41 ; U6.7@805.93,2096.79 807.1,2096.79 808.87,2098.56 808.87,2132.05 800.96,2139.96 782.29,2139.96 773.1,2149.16 773.1,2243.09 794.02,2264.01 808.26,2264.01 v1(822.2,2277.95)
  Bottom Layer w5.9: v1(756.31,2765.09) 756.31,2730.09 837.41,2648.99 837.41,2423.89 849.38,2411.92 849.38,2348.55 813.56,2312.73 813.56,2288.87 822.2,2280.23 v1(822.2,2277.95)
LVDS_D0_MODULE_WAKEUP_GPIO_2: U1.3 U6.1 | length 2768.1
  Top Layer w5.9: v1(731.31,2725.09) 690.31,2766.09 657.31,2766.09 586.98,2836.42 586.98,3404.77 604.8,3422.59 937.81,3422.59 958.31,3402.09 1418.31,3402.09 1476.95,3460.74 1476.95,3504.74 1504.6,3532.39 1714.07,3532.39 1760.44,3486.02 U1.3@1783.45,3486.02 ; v1(830.36,2377.32) 830.36,2375.67 929.94,2276.08 U6.1@929.94,2122.38
  Bottom Layer w5.9: v1(731.31,2725.09) 731.31,2707.87 752.21,2686.96 774.44,2686.96 822.31,2639.09 822.31,2385.54 830.36,2377.49 v1(830.36,2377.32)
LVDS_D1_CAN_FD_RX_SPI_RS232_CTRL_GPIO_3: U1.9 U6.3 | length 2767.3
  Top Layer w5.9: v1(681.31,2725.09) 660.31,2746.09 626.14,2746.09 542.14,2830.09 256.31,2830.09 249.31,2837.09 249.31,2852.09 256.03,2858.82 508.03,2858.82 532.16,2882.94 532.16,3501.94 553.26,3523.04 1045.36,3523.04 1056.24,3512.16 1056.24,3496.47 1045.79,3486.02 U1.9@980.3,3486.02 ; v1(818.41,2351.68) 836.13,2351.68 902.52,2285.29 902.52,2165.51 890.7,2153.7 890.7,2144.08 890.67,2144.04 U6.3@890.67,2122.47
  Bottom Layer w5.9: v1(681.31,2725.09) 740.31,2666.09 768.31,2666.09 809.58,2624.82 809.58,2360.51 v1(818.41,2351.68)
LVDS_D2_CAN_FD_TX: U1.22 U6.4 | length 2767.5
  Top Layer w5.9: v1(808.31,2763.09) 808.31,2793.09 788.31,2813.09 767.31,2813.09 735.43,2844.97 735.43,3213.22 745.63,3223.42 915.7,3223.42 956.15,3263.86 1546.08,3263.86 1556.31,3274.09 1556.31,3326.08 1595.32,3365.09 1664.31,3365.09 1785.31,3244.09 1843.31,3244.09 1876.31,3211.09 1876.31,3177.74 2016.85,3037.2 U1.22@2051.17,3037.2 ; v1(868.45,2251.35) 888.93,2230.87 888.93,2168.76 870.89,2150.71 U6.4@870.89,2122.38
  Bottom Layer w5.9: v1(808.31,2763.09) 833.31,2763.09 878.31,2718.09 878.31,2470.58 885.85,2463.03 885.85,2268.75 868.91,2251.81 v1@868.45,2251.81
LVDS_D3_PRESENCE_INDICATION_GPIO: U1.2 U6.6 | length 2767.7
  Top Layer w5.9: v1(801.31,2725.09) 800.31,2725.09 781.31,2744.09 781.31,2769.09 761.31,2789.09 732.24,2789.09 686.36,2834.97 686.36,3261.15 695.63,3270.42 926.14,3270.42 936.51,3280.79 1462.01,3280.79 1589.46,3408.25 1589.46,3493.02 1611.57,3515.13 1710.82,3515.13 1800.29,3425.66 1831.87,3425.66 1892.23,3486.02 U1.2@1917.31,3486.02 ; U6.6@831.19,2122.7 831.19,2147.05 824.95,2153.3 793.29,2153.3 785,2161.6 785,2226.44 805.71,2247.15 826.42,2247.15 830.4,2243.17 v1(833.67,2243.17)
  Bottom Layer w5.9: v1(801.31,2725.09) 851.58,2674.82 851.58,2444.91 861.36,2435.13 861.36,2335.71 848.12,2322.47 848.12,2257.62 v1(833.67,2243.17)
LVDS_FRCLK_HOST_CLK_REQ: U1.24 U6.9 | length 2768.1
  Top Layer w5.9: U6.9@805.69,2057.66 791.56,2057.66 761.2,2088.03 761.2,2263.83 798.63,2301.27 857.45,2301.27 v1(866.2,2292.52) ; v1(843.31,2724.09) 865.31,2724.09 883.31,2742.09 883.31,2857.09 870.31,2870.09 795.31,2870.09 789.19,2876.21 789.19,3154.13 801.88,3166.82 920.04,3166.82 927.31,3174.09 927.31,3209.28 965.02,3246.99 1372.41,3246.99 1393.31,3226.09 1551.31,3226.09 1581.31,3256.09 1581.31,3294.09 1604.31,3317.09 1645.31,3317.09 1736.31,3226.09 1817.31,3226.09 1846.31,3197.09 1846.85,3197.09 1846.85,3143.13 1783.45,3079.74 U1.24@1783.45,3037.2
  Bottom Layer w5.9: v1(843.31,2724.09) 863.88,2703.52 863.88,2463.26 873.95,2453.19 873.95,2325.74 866.2,2317.99 v1(866.2,2292.52)
MCU_3V3: C58.1 J14.1 J24.2 | length 3080
  L3_PWR1 w12: J24.2@158.99,423.6 104.86,477.72 104.86,693.82 277.54,866.5 277.54,1546.95 253.7,1570.79 253.7,1829.02 335.5,1910.82 335.5,2078.44 257.45,2156.49 257.45,2626.24 317.18,2685.96 317.18,2737.32 354.72,2774.87 409.53,2774.87 429.31,2755.09 429.31,2658.79 v1(460,2628.1)
  Bottom Layer w12: v1(460,2628.1) 500.08,2588.02 738.21,2588.02 J14.1@739.01,2587.22
MCU_5V: C60.1 J14.2 J22.2 R116.2 | length 2720.4
  Top Layer w25: v1(395.31,2504.09) 480.31,2504.09 521.31,2545.09 609.31,2545.09 649.31,2585.09 1036.76,2585.09 1067.93,2616.27 v1(1068.2,2616.27)
  Bottom Layer w22: J14.2@961.45,2587.22 1014.18,2587.22 1034.11,2567.29 C60.1@1054.07,2567.29 R116.2@1102.94,2567.29 1102.94,2596.46 1083.13,2616.27 v1(1068.2,2616.27)
  Bottom Layer w40: J22.2@158.99,953.82 254.04,953.82 355.62,1055.41 355.62,1617.41 429.31,1691.09 429.31,1816.09 374.37,1871.03 374.37,2206.56 338.31,2242.63 338.31,2447.09 v1(395.31,2504.09)
MOD_WU_GPIO_2: R14.1 R19.2 R42.2 R140.2 U6.23 | length 4862.6
  Top Layer w5.9: U6.23@955.53,2077.1 955.62,2077.19 976.27,2077.19 995.4,2096.32 R19.2@1037.4,2096.32 1037.4,2149.61 1037.03,2149.98 1037.03,2168.12 1022.2,2182.95 v1(1022.2,2240.31) 1022.86,2240.97 1097.43,2240.97 1143.2,2195.2 1143.2,2031.01 1122.01,2009.83 1122.01,1979.14 1237.86,1863.3 1246.36,1863.3 1260.3,1849.36 1260.3,1779.29 1206.67,1725.66 1206.67,1637.42 1161.23,1591.98 1161.23,1510.68 1188.68,1483.24 1188.68,1366.53 1211.41,1343.79 1307.3,1343.79 1414.86,1451.35 1789.41,1451.35 1865.64,1375.13 1983.19,1375.13 2024.65,1333.66 R42.2@2024.65,1311.85
  L3_PWR1 w5.9: v1(1022.2,2240.31) 1022.2,2350.99 1227,2555.79 1495.18,2555.79 1525.05,2585.66 1623.01,2585.66 1635.52,2598.17 1635.52,2605.61 1653.91,2623.99 1756.32,2623.99 1852.91,2720.58 2062.24,2720.58 2203.59,2579.24 2265.58,2579.24 2278.01,2566.81 2414.74,2566.81 2561.38,2713.45 v1(2639.27,2713.45)
  Bottom Layer w5.9: v1(2639.27,2713.45) 2730.02,2713.45 2812.2,2631.26 2812.2,2363.56 2785.38,2336.74 R140.2@2785.38,2289.32
MODE_1V8: R79.2 R84.2 U13.3 | length 132.2
  Top Layer w5.9: U13.3@1734.53,832.68 1734.53,800.1 1744.47,790.16 R79.2@1744.47,764.37 1744.47,735.95 1751.6,728.83 R84.2@1751.6,709.1 R84.2@1752.68,708.02
MODE_3V3: R199.2 R200.2 U15.3 | length 117.4
  Top Layer w5.9: U15.3@1443.1,735.85 v1@1475.73,735.85
  Bottom Layer w5.9: R199.2@1423.29,702.41 1473.06,702.41 R200.2@1475.31,704.66 1475.32,735.43 v1(1476.02,736.14)
MUX_CTRL_FTDI_DCA_LP_XDS_RS232: R105.1 S1.5 U16.1 U16.5 | length 1305
  Top Layer w5.9: v1(1579.19,2016.66) 1579.28,2016.58 S1.5@1579.28,1971.68
  Bottom Layer w5.9: v1@1565.27,2730.26 1565.27,2749.66 1586.76,2771.15 U16.5@1655.91,2771.15 ; v1(1579.19,2016.66) 1579.29,2016.76 1579.29,2103.19 1604.04,2127.94 1604.04,2293.93 1568.99,2328.98 1513.22,2328.98 1351.28,2490.92 1351.28,2560.05 1471.76,2680.54 1471.76,2731.42 1488.58,2748.24 1547.56,2748.24 v1(1565.53,2730.26) 1565.53,2706.41 R105.1@1565.27,2706.15 1605.76,2706.15 1619.5,2692.41 U16.1@1655.91,2692.41
MUX_CTRL_FTDI_DCA_RS232: R144.1 S1.7 U19.1 U19.5 | length 1062.6
  Top Layer w5.9: S1.7@1479.28,1971.68 1481.28,1969.68 1481.28,1919.92 1507.92,1893.28 1578.74,1893.28 1593.01,1907.55 1829.28,1907.55 1903.82,1982.09 2032.53,1982.09 2082.31,2031.87 2082.31,2069.41 v1(2097.69,2084.79)
  Bottom Layer w5.9: v1(2097.69,2084.79) 2097.69,2106.92 2111.08,2120.3 R144.1@2139.97,2120.3 2189.47,2120.3 U19.5@2191.89,2117.88 2191.89,2151.63 2205.13,2164.87 2259.42,2164.87 2270.64,2153.65 U19.1@2270.63,2117.88
MUX_CTRL_FTDI_DCA_SPI: R177.2 S1.6 U21.11 U21.21 | length 1080.4
  Top Layer w5.9: v1(1230.19,1549.08) 1231.31,1547.97 1231.31,1458.31 1286.57,1403.05 1343.53,1403.05 1403.73,1463.25 1413.6,1463.25 v1(1443.76,1493.41) ; v1(1512.8,1919.36) 1515.91,1919.36 1529.28,1932.72 S1.6@1529.28,1971.68
  Bottom Layer w5.9: v1(1230.19,1549.08) U21.21@1255.75,1549.12 ; U21.11@1405.36,1529.43 1441.86,1529.43 R177.2@1443.69,1531.27 ; v1(1443.76,1493.41) 1443.69,1493.48 R177.2@1443.69,1531.27 ; v1(1512.8,1919.36) 1456.44,1919.36 1413.75,1876.66 1413.75,1823.43 1445.26,1791.92 1452.4,1791.92 1510.36,1733.95 1510.36,1605.24 1497.81,1592.68 1497.81,1566.91 1484.11,1553.22 1451.77,1553.22 1443.69,1545.14 R177.2@1443.69,1531.27
MUX_CTRL_LVDS_CAN_GPIO_TP: R23.2 S1.2 U6.11 U6.21 | length 1990.8
  Top Layer w5.9: v1(760.31,2045.09) 787.35,2018.05 U6.11@805.93,2018.05 ; U6.21@955.53,2037.73 1007.89,2037.73 1020.61,2050.45 R23.2@1035.57,2050.45 1034.74,2049.62 v1(1034.74,2026.87) ; v1(1048.28,2310.93) 1072.24,2286.97 1141.43,2286.97 1199.31,2229.09 1199.31,2169.09 1235.31,2133.09 1298.47,2133.09 1321.69,2156.31 1658.73,2156.31 1729.28,2085.76 S1.2@1729.28,1971.68
  L3_PWR1 w5.9: v1(1034.74,2026.87) 1034.74,2226.23 1048.35,2239.85 1048.35,2310.86 v1(1048.28,2310.93)
  Bottom Layer w5.9: v1(760.31,2045.09) 698.31,2045.09 680.31,2063.09 680.31,2122.09 703.3,2145.09 829.11,2145.09 858.31,2115.89 858.31,2077.32 869.26,2066.37 888.51,2066.37 899.52,2055.36 899.52,2037.73 908.47,2028.78 1032.83,2028.78 v1(1034.74,2026.87)
MUX_CTRL_SPI_I2C: R149.1 S1.3 U20.1 U20.5 | length 955.8
  Top Layer w5.9: v1(1210.08,2025.99) 1253.01,2025.99 1271.87,2044.86 1271.87,2077.32 1338.96,2144.41 1644.27,2144.41 1679.28,2109.4 S1.3@1679.28,1971.68
  Bottom Layer w5.9: U20.1@1122.48,1938.43 1122.48,1899.52 1140.05,1881.95 1190.57,1881.95 1201.34,1892.72 U20.5@1201.34,1938.3 ; U20.5@1201.22,1938.43 1201.22,1999.33 R149.1@1204.41,2002.52 1204.41,2020.33 v1(1210.08,2025.99)
MUX_CTRL_XDS_DCA_LP_JTAG: R108.1 S1.4 U17.1 | length 2470.4
  Top Layer w5.9: v1(1231.69,2257.16) 1257.76,2231.09 1651.03,2231.09 1828.52,2053.61 1828.52,1951.39 1798.14,1921.01 1642.32,1921.01 1629.28,1934.05 S1.4@1629.28,1971.68 ; v1(1259.16,2616.79) 1306.08,2663.71 1611.26,2663.71 1623.24,2651.73 1689.5,2651.73 1700.4,2640.84 1861.66,2640.84 1937.87,2717.05 2038.93,2717.05 2057.19,2698.79 2057.19,2653.01 v1(2077.76,2632.43)
  Bottom Layer w5.9: v1(1231.69,2257.16) 1231.69,2392 1253.78,2414.08 1282.67,2414.08 1298.16,2429.57 1298.16,2532.73 1269.31,2561.58 1269.31,2606.63 v1(1259.16,2616.79) ; v1(2077.76,2632.43) 2083.53,2626.66 2114.26,2626.66 U17.1@2146.33,2626.66
MUX_SPI_BUZY: R174.1 U21.7 | length 80.2
  Bottom Layer w5.9: U21.7@1405.36,1608.17 1405.36,1632.83 1420.57,1648.05 R174.1@1454.61,1648.05
MUX_SPI_CLK_I2C_SCL: R164.1 U20.10 | length 64.8
  Bottom Layer w5.9: R164.1@1058.83,1760.54 1081.22,1760.54 1083.91,1763.23 U20.10@1122.48,1763.23
MUX_SPI_CS_I2C_SDA: R171.1 U20.6 | length 67.8
  Bottom Layer w5.9: U20.6@1201.22,1763.23 1201.22,1719.3 1204.66,1715.86 1204.66,1697 R171.1@1204.56,1696.9
MUX_SPI_MISO: R168.1 U21.4 | length 95.6
  Bottom Layer w5.9: R168.1@1296.07,1710.67 1296.56,1710.67 1302.96,1704.27 1302.96,1703.78 1340.4,1666.35 U21.4@1340.4,1633.76
MUX_SPI_MOSI: R169.1 U21.6 | length 73.5
  Bottom Layer w5.9: U21.6@1379.77,1633.76 1379.77,1653.76 1405.42,1679.42 R169.1@1405.42,1696.66
MUX_TCK_R: R104.1 U17.4 | length 73
  Bottom Layer w5.9: v1(2182.44,2679.22) 2185.71,2679.22 2190.54,2674.39 2205.52,2674.39 R104.1@2205.72,2674.19 2205.72,2627 U17.4@2205.38,2626.66
MUX_TDI_R: R103.1 U17.7 | length 49.8
  Bottom Layer w5.9: U17.7@2264.44,2626.66 2264.44,2673.08 R103.1@2263.32,2674.19 R103.1@2264.6,2675.46
MUX_TDO_R: R130.1 U17.9 | length 49.7
  Bottom Layer w5.9: R130.1@2280.17,2460.46 2284.12,2464.42 U17.9@2284.12,2508.55
MUX_TMS_R: R129.1 U17.12 | length 47.3
  Bottom Layer w5.9: R129.1@2225.07,2461.24 U17.12@2225.07,2508.55
NetC9_2: C9.2 C10.2 R22.1 U5.1 U18.9 | length 229.2
  Top Layer w5.9: v1(1430.42,2032.8) 1442.91,2045.29 C9.2@1459.75,2045.29 C10.2@1492.06,2045.29 ; C10.2@1492.61,2044.74 1515.11,2044.74 1524.8,2054.43 R22.1@1545.22,2054.43 U5.1@1545.21,2107.41
  Bottom Layer w5.9: U18.9@1381.98,2022.43 1420.05,2022.43 v1(1430.42,2032.8)
NetC15_2: C15.2 R20.1 U7.3 | length 103.5
  Top Layer w20: U7.3@438.19,2020.7 479.75,2020.7 481.57,2018.88 C15.2@498.41,2018.88 498.08,2019.21 R20.1@498.08,2061.3
NetC16_2: C16.2 R21.2 R24.1 | length 338.4
  Top Layer w5.9: R24.1@145.33,1931.33 145.82,1930.84 145.82,1872.26 v1(154.03,1864.05) ; R21.2@145.33,2060.07 v1@145.33,2092.23
  Bottom Layer w5.9: v1(145.34,2092.24) 158.27,2079.32 158.27,1871.56 154.03,1867.33 v1(154.03,1864.05)
NetC62_2: C62.2 R135.2 U18.68 | length 98.5
  Bottom Layer w5.9: U18.68@1982.42,2337.65 2044.37,2337.65 C62.2@2045.48,2338.76 2044.29,2339.95 R135.2@2044.29,2373.28
NetC65_2: C65.2 U18.88 Y1.1 | length 280.9
  Bottom Layer w5.9: U18.88@1988.28,2022.43 2026.65,2022.43 2053.79,1995.29 C65.2@2084.03,1995.29 2099.6,1995.29 2117.25,1977.64 2201.84,1977.64 2206.11,1981.92 Y1.1@2206.11,2024.64
NetC66_2: C66.2 U18.89 Y1.3 | length 185.8
  Bottom Layer w5.9: U18.89@1988.28,2006.68 2018.1,2006.68 2038.95,1985.83 2038.95,1970.96 2065,1944.91 C66.2@2084.03,1944.91 2100.2,1944.91 2107.67,1937.45 2107.67,1937.35 2110.93,1934.09 Y1.3@2135.24,1934.09
NetC69_1: C69.1 R166.1 U18.96 | length 164.3
  Bottom Layer w5.9: U18.96@1988.28,1896.44 1988.28,1824.7 2013.82,1799.16 2033.43,1799.16 2035.56,1797.03 R166.1@2035.56,1763.23
NetC85_1: C85.1 R185.1 U10.6 | length 112.9
  Top Layer w10: v1(2737.41,1345.21) 2740.69,1345.21 2745.8,1350.33 U10.6@2760.01,1350.33
  Bottom Layer w10: R185.1@2696.11,1321.6 2720.97,1321.6 2735.88,1336.51 2735.88,1343.68 v1(2737.41,1345.21) v1(2737.41,1345.21) 2745.58,1353.31 C85.1@2766.98,1353.31
NetD1_1: D1.1 R107.1 | length 65.5
  Top Layer w8: v1(278.57,2702.82) 305.57,2702.82 D1.1@307.42,2704.68
  Bottom Layer w8: R107.1@272.35,2669.53 272.35,2693.33 278.57,2699.55 v1(278.57,2702.82)
NetD1_2: D1.2 Q1.3 | length 81.8
  Top Layer w8: D1.2@342.86,2704.68 343.08,2704.9 343.08,2727.87 v1(343.31,2728.09)
  Bottom Layer w8: Q1.3@309.53,2759.64 309.76,2759.87 330.53,2759.87 343.31,2747.09 v1(343.31,2728.09)
NetD2_1: D2.1 R128.1 | length 55.1
  Top Layer w8: v1(1228.71,2486.02) 1231.99,2486.02 1238.35,2492.38 1251.66,2492.38 D2.1@1254.63,2495.35
  Bottom Layer w8: v1(1228.71,2486.02) 1231.99,2486.02 1238.13,2479.88 R128.1@1251.52,2479.88
NetD2_2: D2.2 Q2.3 | length 162.7
  Top Layer w8: v1(1272.32,2531.62) 1290.06,2513.89 D2.2@1290.06,2495.35
  Bottom Layer w8: Q2.3@1227.59,2632.2 1227.59,2608.96 1251.52,2585.04 1251.52,2552.43 v1(1272.32,2531.62)
NetD3_2: D3.2 L1.2
NetD4_2: D4.2 R188.2 | length 119.3
  Top Layer w5.9: v1(1667.88,1144.59) 1668.52,1145.22 D4.2@1668.52,1182.12
  Bottom Layer w5.9: R188.2@1663.53,1224.3 1665.28,1222.54 1665.28,1165.39 1667.88,1162.79 v1(1667.88,1144.59)
NetD6_2: D6.2 FB1.2 FB2.2
NetD8_1: D8.1 R88.1 | length 46.7
  Top Layer w5.9: R88.1@668.94,543.18 710.61,543.18 D8.1@714.19,539.6
NetD8_2: D8.2 Q3.3 | length 78.3
  Top Layer w5.9: D8.2@714.19,596.69 732.6,596.69 737.53,601.62 748.11,601.62 v1(749.03,602.54)
  Bottom Layer w5.9: Q3.3@710.09,607.51 722,607.51 726.98,602.54 v1(749.03,602.54)
NetD9_1: D9.1 R93.1 | length 49.4
  Top Layer w10: R93.1@1951.09,154.47 D9.1@2000.53,154.47
NetJ6_26: J6.26 R64.1 | length 109.5
  Top Layer w4: J6.26@594.31,970.21 633.5,970.21 638.35,965.37 653.69,965.37 ; 653.71,965.34 687.83,965.34 697.34,974.85 R64.1@697.34,975.34
NetJ6_28: J6.28 R66.1 | length 109.5
  Top Layer w4: J6.28@594.31,950.52 633.5,950.52 638.35,955.37 649.55,955.37 ; 649.57,955.34 687.83,955.34 697.34,945.83 R66.1@697.34,945.34
NetJ6_32: J6.32 R67.1 | length 198.2
  Top Layer w4: J6.32@594.31,911.15 633.5,911.15 638.35,906.31 775.61,906.31 785.77,916.47 R67.1@785.77,916.96
NetJ6_34: J6.34 R68.1 | length 197.6
  Top Layer w4: J6.34@594.31,891.47 633.5,891.47 638.35,896.31 776.91,896.31 785.77,887.45 R68.1@785.77,886.96
NetJ6_38: J6.38 R69.1 | length 109.6
  Top Layer w4: J6.38@594.31,852.1 633.5,852.1 638.49,847.11 687.53,847.11 697.34,856.92 R69.1@697.34,857.41
NetJ6_40: J6.40 R71.1 | length 109.3
  Top Layer w4: J6.40@594.31,832.41 633.5,832.41 638.2,837.11 688.13,837.11 697.34,827.9 R71.1@697.34,827.41
NetJ6_44: J6.44 R73.1 | length 197.9
  Top Layer w4: J6.44@594.31,793.04 633.5,793.04 638.35,788.2 690.9,788.2 776.26,788.2 785.77,797.71 R73.1@785.77,798.2
NetJ6_46: J6.46 R78.1 | length 197.9
  Top Layer w4: J6.46@594.31,773.36 633.5,773.36 638.35,778.2 695.04,778.2 776.26,778.2 785.77,768.69 R78.1@785.77,768.2
NetJ6_50: J6.50 R81.1 | length 109.5
  Top Layer w4: J6.50@594.31,733.99 633.5,733.99 638.35,729.15 653.69,729.15 687.83,729.15 697.34,738.65 R81.1@697.34,739.15
NetJ6_51: J6.51 R80.2 | length 114.1
  Top Layer w5.9: R80.2@284.45,752.08 304.23,752.08 311.31,745 311.31,720.72 317.73,714.3 J6.51@368.72,714.3
NetJ6_52: J6.52 R83.1 | length 109.5
  Top Layer w4: J6.52@594.31,714.3 633.5,714.3 638.35,719.15 649.55,719.15 687.83,719.15 697.34,709.64 R83.1@697.34,709.15
NetJ6_53: J6.53 R82.2 | length 92
  Top Layer w5.9: R82.2@284.45,713.22 303.05,694.62 J6.53@368.72,694.62
NetJ6_55: J6.55 R86.2 | length 84.6
  Top Layer w5.9: R86.2@284.45,674.23 285.15,674.93 J6.55@368.72,674.93
NetJ6_56: J6.56 R85.1 | length 197.6
  Top Layer w4: J6.56@594.31,674.93 633.5,674.93 638.01,670.42 775.08,670.42 776.91,672.25 778.42,672.25 785.77,679.6 R85.1@785.77,680.09
NetJ6_57: J6.57 R89.2 | length 180.2
  Top Layer w5.9: R89.2@257.26,551.72 257.26,595.93 316.58,655.25 J6.57@368.72,655.25
NetJ6_58: J6.58 R87.1 | length 342.7
  Top Layer w4: J6.58@594.31,655.25 J6.58@633.5,655.25 ; R87.1@785.77,650.09 785.77,650.58 775.93,660.42 ; J6.58@633.5,655.25 J6.58@638.68,660.42 ; J6.58@633.5,655.25 J6.58@638.68,660.42 ; J6.58@638.68,660.42 770.94,660.42 775.93,660.42 ; J6.58@638.68,660.42 775.93,660.42
NetJ6_59: J6.59 R90.2 | length 140.1
  Top Layer w5.9: R90.2@300.86,551.72 300.86,615.8 320.62,635.56 J6.59@368.72,635.56
NetJ14_5: J14.5 R134.2 | length 69.3
  Bottom Layer w5.9: R134.2@670.04,2386.52 670.73,2387.22 J14.5@739.01,2387.22
NetJ14_7: J14.7 R141.2 | length 69.3
  Bottom Layer w5.9: R141.2@670.04,2287.98 670.8,2287.22 J14.7@739.01,2287.22
NetJ14_17: J14.17 R162.2 | length 88.1
  Bottom Layer w5.9: R162.2@651.56,1785.6 653.18,1787.22 J14.17@739.01,1787.22
NetJ14_19: J14.19 R172.2 | length 81.1
  Bottom Layer w5.9: R172.2@658.16,1687.88 658.82,1687.22 J14.19@739.01,1687.22
NetJ15_1: J15.1 R111.2 | length 73.2
  Bottom Layer w5.9: R111.2@2365.65,2587.21 J15.1@2438.83,2587.21
NetJ15_3: J15.3 R126.2 | length 72.1
  Bottom Layer w5.9: R126.2@2366.77,2487.22 J15.3@2438.83,2487.22
NetJ15_4: J15.4 R127.1 | length 81
  Bottom Layer w5.9: J15.4@2661.27,2487.22 2661.82,2486.67 R127.1@2742.02,2486.67
NetJ15_5: J15.5 R132.2 | length 80.2
  Bottom Layer w5.9: R132.2@2358.64,2387.22 J15.5@2438.83,2387.22
NetJ15_6: J15.6 R133.1 | length 80.8
  Bottom Layer w5.9: J15.6@2661.27,2387.21 2661.41,2387.08 R133.1@2742.02,2387.08
NetJ15_7: J15.7 R138.2 | length 78.5
  Bottom Layer w5.9: R138.2@2360.37,2287.22 J15.7@2438.83,2287.22
NetJ15_8: J15.8 R140.1 | length 84.6
  Bottom Layer w5.9: J15.8@2661.27,2287.22 2663.38,2289.32 R140.1@2745.03,2289.32
NetJ15_11: J15.11 R146.2 | length 85.9
  Bottom Layer w5.9: R146.2@2354.21,2089.83 2356.83,2087.22 J15.11@2439.01,2087.22
NetJ15_13: J15.13 R148.2 | length 75.8
  Bottom Layer w5.9: R148.2@2363.03,1987.22 J15.13@2438.83,1987.22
